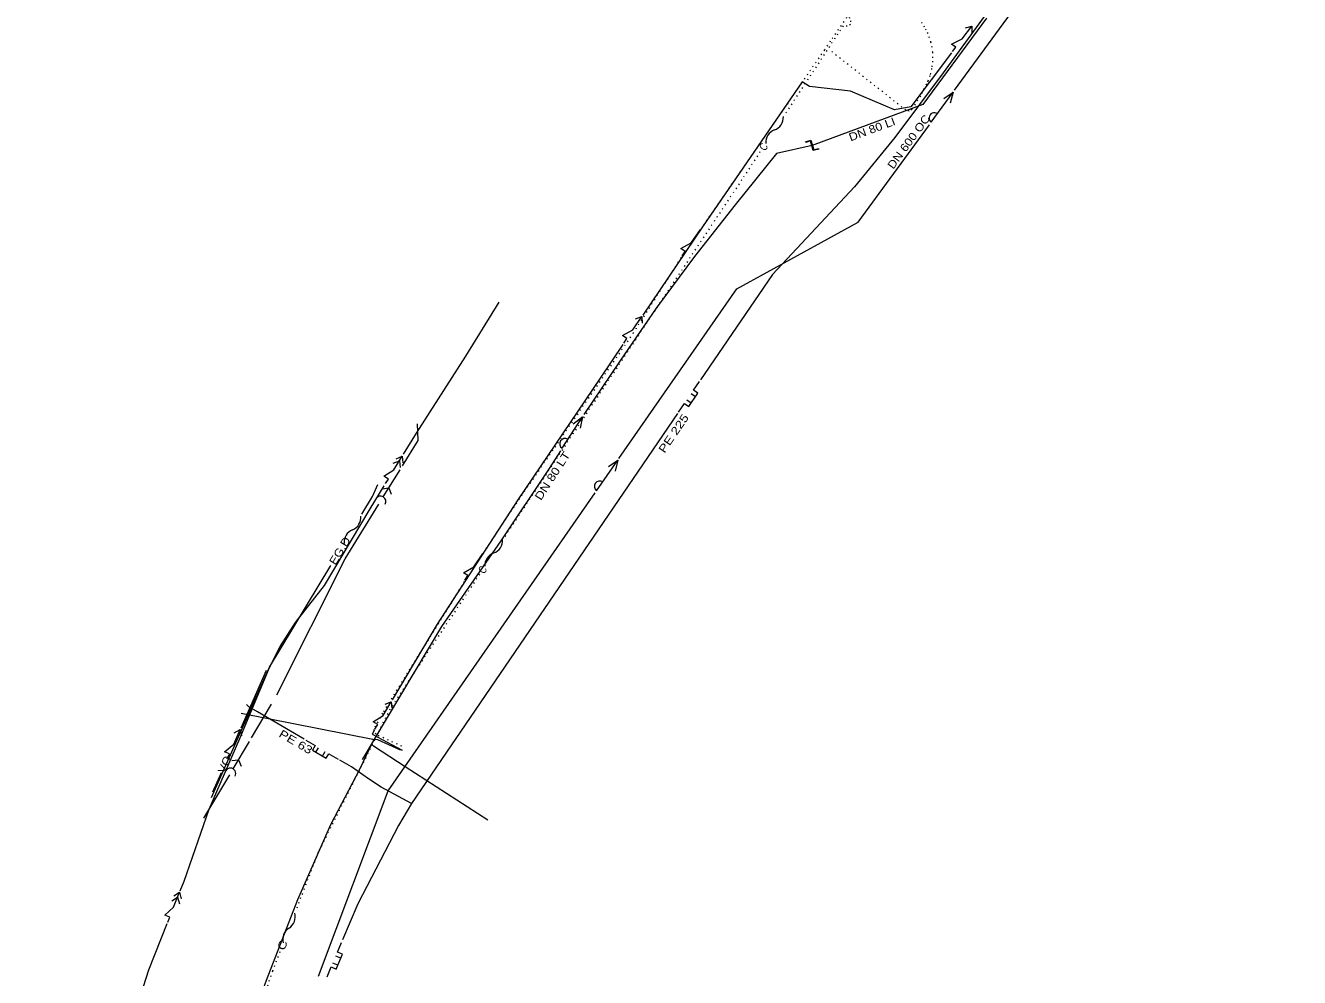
# Model space of a CAD drawing. Extents: x -601552 to -601367, y -1161450 to -1160710.
# Drawn here: x -601531.6 to -601412.2, y -1160922.2 to -1160833 of the extents above; entities that cross this region are included whole.
import ezdxf
from ezdxf.enums import TextEntityAlignment as Align

# ---------------------------------------------------------------- set-up
doc = ezdxf.new("R2010")
doc.units = 0
doc.header["$LTSCALE"] = 0.3
doc.linetypes.add('DOTTED', pattern=[1.5, 0.3, -1.2])
for name, color, linetype, lineweight in [('27', 7, 'Continuous', 13), ('34', 7, 'Continuous', 13), ('41', 7, 'Continuous', 13), ('42', 7, 'DOTTED', 13), ('54', 7, 'Continuous', 13), ('56', 7, 'Continuous', 13), ('57', 7, 'Continuous', 13), ('58', 7, 'Continuous', 13), ('59', 7, 'Continuous', 13)]:
    doc.layers.add(name, color=color, linetype=linetype, lineweight=lineweight)

msp = doc.modelspace()

# ---------------------------------------------------------------- linework, layer by layer
at = {"layer": '27'}
for points in [[(-601500.071, -1160878.775), (-601499.08, -1160877.13), (-601498.587, -1160876.005)], [(-601514.164, -1160905.317), (-601508.72, -1160893.13), (-601502.977, -1160883.598)]]:
    msp.add_lwpolyline(points, dxfattribs=at)
for centre, start, end in [((-601501.4267, -1160879.0872), 292.06131, 5.80111), ((-601500.4877, -1160881.4042), 112.06131, 185.80111)]:
    msp.add_arc(centre, 1.25, start, end, dxfattribs=at)
at = {"layer": '34', "linetype": 'DOTTED'}
for points in [[(-601453.58, -1160830.97), (-601454.43, -1160832.21), (-601454.29, -1160832.57), (-601454.3, -1160832.91), (-601454.61, -1160833.07), (-601454.99, -1160833.04), (-601460.433, -1160841.306)], [(-601462.754, -1160844.829), (-601464.48, -1160847.45), (-601486.766, -1160880.977)], [(-601489.054, -1160884.418), (-601497.45, -1160897.05), (-601504.17, -1160910.45), (-601506.269, -1160915.904)], [(-601507.77, -1160919.803), (-601508.1, -1160920.66), (-601508.46, -1160921.59)], [(-601508.46, -1160921.59), (-601514.29, -1160938.92), (-601523.126, -1160975.284)]]:
    msp.add_lwpolyline(points, dxfattribs=at)
at = {"layer": '34'}
for centre, start, end in [((-601461.8311, -1160841.6097), 289.76238, 3.50218), ((-601460.9858, -1160843.9625), 109.76238, 183.50218), ((-601488.1411, -1160881.2393), 289.51741, 3.25721), ((-601487.3059, -1160883.5956), 109.51741, 183.25721), ((-601507.5703, -1160916.5002), 302.07755, 15.81735), ((-601506.2427, -1160918.6185), 122.07755, 195.81735)]:
    msp.add_arc(centre, 1.25, start, end, dxfattribs=at)
at = {"layer": '41'}
for p, q in [((-601494.812, -1160871.883), (-601494.861, -1160870.319)), ((-601496.279, -1160874.262), (-601494.812, -1160871.883)), ((-601498.071, -1160877.168), (-601496.496, -1160874.614)), ((-601501.656, -1160882.983), (-601498.482, -1160877.835)), ((-601508.055, -1160895.704), (-601501.656, -1160882.983)), ((-601510.411, -1160899.742), (-601508.534, -1160896.581)), ((-601512.136, -1160902.647), (-601510.604, -1160900.067)), ((-601514.882, -1160907.27), (-601512.467, -1160903.204))]:
    msp.add_line(p, q, dxfattribs=at)
for points in [[(-601498.181, -1160876.395), (-601497.546, -1160876.317), (-601497.33, -1160876.92)], [(-601512.26, -1160901.876), (-601511.626, -1160901.787), (-601511.4, -1160902.386)]]:
    msp.add_lwpolyline(points, dxfattribs=at)
for centre, start, end in [((-601498.333, -1160877.5935), 328.34299, 148.34299), ((-601512.3916, -1160903.0766), 329.29489, 149.29489)]:
    msp.add_arc(centre, 0.5, start, end, dxfattribs=at)
at = {"layer": '42'}
for points in [[(-601445.656, -1160819.108), (-601449.96, -1160825.423), (-601456.184, -1160834.473)], [(-601447.638, -1160832.708), (-601447.427, -1160833.028), (-601447.256, -1160833.33), (-601447.096, -1160833.657), (-601446.942, -1160834.032), (-601446.79, -1160834.521), (-601446.694, -1160834.942), (-601446.62, -1160835.476), (-601446.595, -1160835.935), (-601446.607, -1160836.327), (-601446.691, -1160837.032), (-601446.855, -1160837.702), (-601447.043, -1160838.218), (-601447.163, -1160838.459), (-601447.183, -1160838.492), (-601447.746, -1160839.598), (-601448.551, -1160840.878), (-601448.808, -1160841.025), (-601449.112, -1160840.935), (-601456.192, -1160835.33)], [(-601456.184, -1160834.473), (-601456.742, -1160835.283), (-601458.87, -1160838.379), (-601468.284, -1160852.012)], [(-601470.141, -1160854.702), (-601470.179, -1160854.756), (-601474.644, -1160861.8), (-601485.33, -1160877.341), (-601488.649, -1160882.31)], [(-601490.48, -1160885.1), (-601498.156, -1160897.437), (-601498.976, -1160898.946), (-601498.823, -1160899.31), (-601498.54, -1160899.495), (-601496.317, -1160900.523)]]:
    msp.add_lwpolyline(points, dxfattribs=at)
at = {"layer": '42', "linetype": 'Continuous'}
for points in [[(-601470.062, -1160854.586), (-601469.778, -1160854.175), (-601470.189, -1160853.891), (-601469.209, -1160853.352), (-601468.357, -1160852.118)], [(-601490.418, -1160884.96), (-601490.141, -1160884.544), (-601490.556, -1160884.267), (-601489.585, -1160883.713), (-601488.752, -1160882.465)]]:
    msp.add_lwpolyline(points, dxfattribs=at)
at = {"layer": '54'}
for p, q in [((-601468.809, -1160867.783), (-601469.222, -1160867.501)), ((-601469.215, -1160868.378), (-601469.628, -1160868.096)), ((-601504.387, -1160901.091), (-601504.134, -1160900.66)), ((-601503.766, -1160901.456), (-601503.513, -1160901.025)), ((-601502.056, -1160920.379), (-601502.516, -1160920.185)), ((-601502.336, -1160921.044), (-601502.797, -1160920.849))]:
    msp.add_line(p, q, dxfattribs=at)
for points in [[(-601434.629, -1160822.427), (-601436.62, -1160825.09), (-601441.77, -1160832.15), (-601445.61, -1160837.44), (-601450.15, -1160843.5), (-601453.92, -1160848.12), (-601461.6, -1160856.34), (-601468.333, -1160866.199)], [(-601470.41, -1160869.241), (-601469.846, -1160868.415), (-601469.433, -1160868.697), (-601468.587, -1160867.458), (-601469, -1160867.176), (-601468.436, -1160866.351)], [(-601470.495, -1160869.365), (-601495.43, -1160905.88), (-601496.64, -1160907.95), (-601500.45, -1160915.29), (-601501.881, -1160918.679)], [(-601505.495, -1160899.862), (-601509.86, -1160897.3), (-601510.66, -1160896.82), (-601510.893, -1160896.607)], [(-601505.33, -1160899.958), (-601504.467, -1160900.465), (-601504.72, -1160900.896), (-601503.427, -1160901.655), (-601503.174, -1160901.224), (-601502.311, -1160901.73)], [(-601495.43, -1160905.88), (-601498.28, -1160904.37), (-601499.45, -1160903.57), (-601501.05, -1160902.47), (-601502.145, -1160901.827)], [(-601503.336, -1160922.126), (-601502.947, -1160921.205), (-601502.486, -1160921.399), (-601501.903, -1160920.017), (-601502.363, -1160919.823), (-601501.974, -1160918.902)]]:
    msp.add_lwpolyline(points, dxfattribs=at)
at = {"layer": '56'}
for p, q in [((-601444.537, -1160839.064), (-601412.215, -1160794.802)), ((-601446.73, -1160842.068), (-601444.666, -1160839.241)), ((-601481.312, -1160872.607), (-601479.409, -1160869.67)), ((-601478.083, -1160876.59), (-601476.087, -1160873.715)), ((-601499.707, -1160901.202), (-601500.036, -1160901.766))]:
    msp.add_line(p, q, dxfattribs=at)
for points in [[(-601441.536, -1160832.32), (-601447.526, -1160840.405), (-601457.885, -1160844.228)], [(-601445.559, -1160839.827), (-601444.666, -1160839.241), (-601444.953, -1160840.27)], [(-601475.985, -1160873.569), (-601464.95, -1160857.68), (-601453.56, -1160851.42), (-601446.896, -1160842.294)], [(-601457.885, -1160844.228), (-601461.232, -1160845.006), (-601465.09, -1160849.785), (-601468.907, -1160854.633), (-601472.516, -1160859.479), (-601475.917, -1160864.447), (-601479.268, -1160869.45)], [(-601480.268, -1160870.305), (-601479.409, -1160869.67), (-601479.638, -1160870.713)], [(-601481.47, -1160872.864), (-601482.526, -1160874.502), (-601487.067, -1160881.279), (-601492.629, -1160889.315), (-601498.966, -1160899.94), (-601499.204, -1160900.358), (-601499.401, -1160900.689), (-601499.707, -1160901.202)], [(-601476.965, -1160874.323), (-601476.087, -1160873.715), (-601476.349, -1160874.75)], [(-601504.142, -1160922.062), (-601497.6, -1160904.69), (-601478.217, -1160876.782)], [(-601498.966, -1160899.94), (-601499.052, -1160899.91), (-601511.378, -1160897.449)], [(-601499.204, -1160900.358), (-601499.003, -1160900.503), (-601496.017, -1160902.418), (-601488.27, -1160907.41)]]:
    msp.add_lwpolyline(points, dxfattribs=at)
msp.add_lwpolyline([(-601457.734, -1160844.641), (-601457.283, -1160844.511), (-601457.266, -1160844.571), (-601457.777, -1160844.718), (-601458.036, -1160843.817), (-601458.487, -1160843.947), (-601458.504, -1160843.887), (-601457.994, -1160843.74)], close=True, dxfattribs=at)
for centre, start, end in [((-601446.4356, -1160841.6638), 53.86138, 233.86138), ((-601481.0403, -1160872.1876), 57.07169, 237.07169), ((-601477.7983, -1160876.1791), 55.21874, 235.21874)]:
    msp.add_arc(centre, 0.5, start, end, dxfattribs=at)
at = {"layer": '57'}
for points in [[(-601444.718, -1160835.443), (-601444.416, -1160835.044), (-601444.814, -1160834.742), (-601443.812, -1160834.247), (-601442.906, -1160833.051)], [(-601443.507, -1160833.223), (-601442.906, -1160833.051), (-601442.909, -1160833.676)], [(-601444.814, -1160835.57), (-601448.632, -1160840.61), (-601450.183, -1160840.906), (-601454.297, -1160839.161), (-601458.148, -1160838.707)], [(-601458.148, -1160838.707), (-601458.805, -1160838.268), (-601468.16, -1160851.859), (-601473.746, -1160860.125)], [(-601475.519, -1160862.749), (-601475.239, -1160862.335), (-601475.653, -1160862.055), (-601474.679, -1160861.506), (-601473.839, -1160860.263)], [(-601474.43, -1160860.468), (-601473.839, -1160860.263), (-601473.809, -1160860.887)], [(-601475.616, -1160862.892), (-601477.751, -1160866.052), (-601485.451, -1160877.434), (-601493.026, -1160889.089), (-601497.23, -1160896.193)], [(-601498.852, -1160898.932), (-601498.597, -1160898.502), (-601499.027, -1160898.247), (-601498.088, -1160897.641), (-601497.324, -1160896.35)], [(-601497.901, -1160896.59), (-601497.324, -1160896.35), (-601497.256, -1160896.972)], [(-601496.31, -1160900.88), (-601496.522, -1160900.861), (-601498.58, -1160899.917), (-601498.884, -1160899.898), (-601499.089, -1160900.135), (-601500.29, -1160902.699), (-601503.007, -1160907.893), (-601506.126, -1160914.909), (-601509.046, -1160922.474), (-601509.347, -1160923.345)], [(-601498.927, -1160899.06), (-601499.124, -1160899.392), (-601496.31, -1160900.88)]]:
    msp.add_lwpolyline(points, dxfattribs=at)
at = {"layer": '58'}
for p, q in [((-601509.062, -1160893.425), (-601511.435, -1160898.833)), ((-601513.274, -1160903.025), (-601514.067, -1160904.833))]:
    msp.add_line(p, q, dxfattribs=at)
for points in [[(-601512.692, -1160901.698), (-601512.491, -1160901.24), (-601512.949, -1160901.039), (-601512.089, -1160900.324), (-601511.486, -1160898.951)], [(-601512.031, -1160899.258), (-601511.486, -1160898.951), (-601511.344, -1160899.559)]]:
    msp.add_lwpolyline(points, dxfattribs=at)
at = {"layer": '59'}
for points in [[(-601496.178, -1160873.169), (-601494.967, -1160871.182), (-601490.327, -1160863.985), (-601487.221, -1160858.931)], [(-601497.854, -1160875.92), (-601497.594, -1160875.493), (-601498.021, -1160875.233), (-601497.074, -1160874.639), (-601496.293, -1160873.358)], [(-601496.873, -1160873.59), (-601496.293, -1160873.358), (-601496.233, -1160873.98)], [(-601497.134, -1160874.017), (-601496.553, -1160873.785), (-601496.493, -1160874.407)], [(-601517.113, -1160914.087), (-601516.741, -1160913.154), (-601514.378, -1160906.426), (-601511.501, -1160899.8), (-601508.747, -1160893.154), (-601507.749, -1160891.184), (-601506.286, -1160888.948), (-601503.585, -1160885.462), (-601499.293, -1160878.281), (-601497.977, -1160876.122)], [(-601518.271, -1160916.997), (-601518.086, -1160916.532), (-601518.551, -1160916.347), (-601517.716, -1160915.603), (-601517.161, -1160914.21)], [(-601517.695, -1160914.536), (-601517.161, -1160914.21), (-601516.998, -1160914.813)], [(-601517.88, -1160915), (-601517.346, -1160914.674), (-601517.183, -1160915.278)], [(-601531.601, -1160963.611), (-601529.22, -1160953.226), (-601526.689, -1160944.051), (-601524.454, -1160935.681), (-601522.748, -1160929.969), (-601520.049, -1160921.46), (-601518.324, -1160917.13)]]:
    msp.add_lwpolyline(points, dxfattribs=at)

# ---------------------------------------------------------------- texts
at = {"layer": '27', "width": 1.15}
msp.add_text('EG.D ', height=0.75, rotation=58.931, dxfattribs=at).set_placement((-601501.7397, -1160882.2715), align=Align.CENTER)
at = {"layer": '34'}
for rotation, width, p in [(56.632, 0.8, (-601461.9734, -1160844.3267)), (56.387, 0.8, (-601488.2963, -1160883.9561)), (68.947, 1.25, (-601507.0089, -1160918.8704))]:
    msp.add_text('C', height=0.75, rotation=rotation, dxfattribs=dict(at, width=width)).set_placement(p, align=Align.RIGHT)
at = {"layer": '54', "width": 1.25}
msp.add_text('PE 225', height=0.75, rotation=55.672, dxfattribs=at).set_placement((-601469.3976, -1160869.729), align=Align.RIGHT)
msp.add_text('PE 63', height=0.75, rotation=329.594, dxfattribs=at).set_placement((-601507.93, -1160899.581))
at = {"layer": '56'}
for s, rotation, width, p in [('DN 600 OC', 53.861, 1.15, (-601446.7676, -1160841.7033)), ('DN 80 LI', 20.257, 1.15, (-601450.0117, -1160842.2845)), ('DN 80 LT', 57.182, 1.2, (-601480.5101, -1160873.2285))]:
    msp.add_text(s, height=0.75, rotation=rotation, dxfattribs=dict(at, width=width)).set_placement(p, align=Align.RIGHT)
at = {"layer": '58', "width": 1.15}
msp.add_text('VO', height=0.75, rotation=66.311, dxfattribs=at).set_placement((-601512.5897, -1160902.4002), align=Align.CENTER)

doc.saveas('drawing.dxf')
